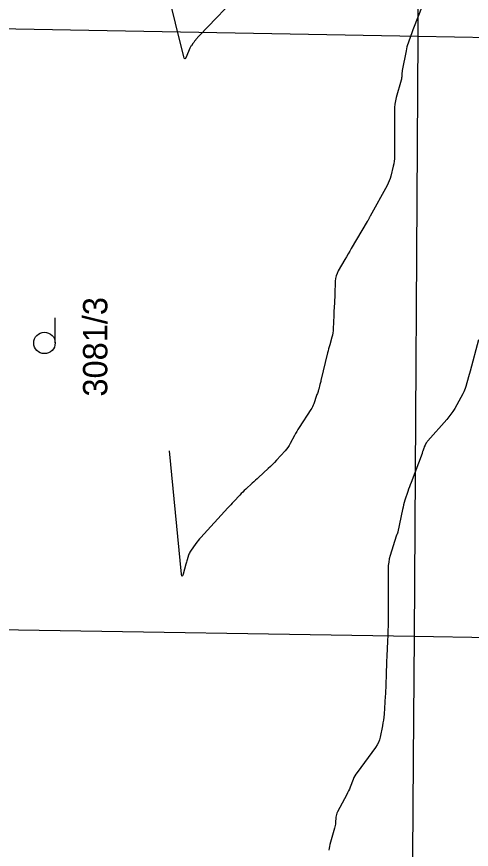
# Model space of a CAD drawing. Extents: x -534410 to -534262, y -1190162 to -1189584.
# Drawn here: x -534356.09 to -534340.2, y -1190052.88 to -1190023.79 of the extents above; entities that cross this region are included whole.
import ezdxf

# ---------------------------------------------------------------- set-up
doc = ezdxf.new("R2010")
doc.units = 0
for name, color, linetype in [('30', 7, 'Continuous'), ('31', 7, 'Continuous'), ('Hranice parcel', 7, 'Continuous'), ('Parcelní čísla', 7, 'Continuous'), ('Značky kultur', 7, 'Continuous')]:
    doc.layers.add(name, color=color, linetype=linetype)

msp = doc.modelspace()

# ---------------------------------------------------------------- linework, layer by layer
at = {"layer": '30'}
msp.add_lwpolyline([(-534341.764, -1190023.028), (-534342.218, -1190024.189), (-534342.243, -1190024.254), (-534342.268, -1190024.319), (-534342.292, -1190024.385), (-534342.315, -1190024.45), (-534342.407, -1190024.713), (-534342.429, -1190024.779), (-534342.448, -1190024.846), (-534342.465, -1190024.913), (-534342.479, -1190024.981), (-534342.613, -1190025.67), (-534342.618, -1190025.698), (-534342.622, -1190025.726), (-534342.625, -1190025.754), (-534342.627, -1190025.782), (-534342.633, -1190025.895), (-534342.635, -1190025.923), (-534342.639, -1190025.951), (-534342.644, -1190025.979), (-534342.651, -1190026.006), (-534342.822, -1190026.621), (-534342.849, -1190026.733), (-534342.868, -1190026.847), (-534342.88, -1190026.961), (-534342.884, -1190027.076), (-534342.884, -1190028.667), (-534342.886, -1190028.756), (-534342.894, -1190028.843), (-534342.908, -1190028.93), (-534342.927, -1190029.017), (-534343.012, -1190029.361), (-534343.036, -1190029.446), (-534343.065, -1190029.529), (-534343.1, -1190029.609), (-534343.141, -1190029.688), (-534343.737, -1190030.764), (-534343.743, -1190030.776), (-534343.749, -1190030.787), (-534343.76, -1190030.81), (-534343.766, -1190030.822), (-534343.772, -1190030.833), (-534343.808, -1190030.898), (-534343.815, -1190030.911), (-534343.822, -1190030.924), (-534343.83, -1190030.936), (-534343.837, -1190030.949), (-534344.393, -1190031.893), (-534344.449, -1190031.988), (-534344.505, -1190032.083), (-534344.56, -1190032.178), (-534344.615, -1190032.273), (-534344.849, -1190032.677), (-534344.891, -1190032.763), (-534344.923, -1190032.851), (-534344.943, -1190032.943), (-534344.952, -1190033.037), (-534344.967, -1190033.493), (-534344.97, -1190033.555), (-534344.972, -1190033.616), (-534344.976, -1190033.678), (-534344.98, -1190033.739), (-534344.997, -1190033.984), (-534345.001, -1190034.045), (-534345.004, -1190034.107), (-534345.007, -1190034.168), (-534345.01, -1190034.23), (-534345.027, -1190034.7), (-534345.031, -1190034.772), (-534345.04, -1190034.843), (-534345.053, -1190034.914), (-534345.071, -1190034.984), (-534345.148, -1190035.262), (-534345.167, -1190035.332), (-534345.185, -1190035.401), (-534345.203, -1190035.471), (-534345.22, -1190035.541), (-534345.453, -1190036.502), (-534345.461, -1190036.537), (-534345.47, -1190036.571), (-534345.479, -1190036.605), (-534345.488, -1190036.639), (-534345.531, -1190036.806), (-534345.537, -1190036.825), (-534345.542, -1190036.844), (-534345.548, -1190036.863), (-534345.555, -1190036.882), (-534345.581, -1190036.956), (-534345.594, -1190036.993), (-534345.607, -1190037.03), (-534345.706, -1190037.315), (-534345.726, -1190037.368), (-534345.749, -1190037.42), (-534345.776, -1190037.47), (-534345.805, -1190037.518), (-534346.218, -1190038.15), (-534346.261, -1190038.217), (-534346.301, -1190038.285), (-534346.341, -1190038.354), (-534346.378, -1190038.423), (-534346.525, -1190038.704), (-534346.564, -1190038.773), (-534346.607, -1190038.839), (-534346.654, -1190038.901), (-534346.706, -1190038.961), (-534347.01, -1190039.292), (-534347.079, -1190039.365), (-534347.15, -1190039.438), (-534347.222, -1190039.508), (-534347.296, -1190039.578), (-534347.632, -1190039.887), (-534347.687, -1190039.938), (-534347.743, -1190039.989), (-534347.799, -1190040.04), (-534347.855, -1190040.091), (-534348.079, -1190040.295), (-534348.134, -1190040.347), (-534348.188, -1190040.399), (-534348.242, -1190040.453), (-534348.294, -1190040.508), (-534348.503, -1190040.733), (-534348.555, -1190040.789), (-534348.606, -1190040.845), (-534348.658, -1190040.901), (-534348.71, -1190040.957), (-534349.651, -1190041.986), (-534349.696, -1190042.036), (-534349.74, -1190042.088), (-534349.782, -1190042.142), (-534349.822, -1190042.196), (-534350.012, -1190042.461), (-534350.034, -1190042.495), (-534350.054, -1190042.531), (-534350.07, -1190042.568), (-534350.083, -1190042.607), (-534350.131, -1190042.765), (-534350.142, -1190042.805), (-534350.154, -1190042.845), (-534350.165, -1190042.884), (-534350.177, -1190042.924), (-534350.274, -1190043.273), (-534350.292, -1190043.326), (-534350.307, -1190043.343), (-534350.319, -1190043.323), (-534350.328, -1190043.268), (-534350.749, -1190038.959)], dxfattribs=at)
at = {"layer": '31'}
for points in [[(-534348.223, -1190022.899), (-534349.701, -1190024.452), (-534349.722, -1190024.474), (-534349.742, -1190024.497), (-534349.763, -1190024.521), (-534349.782, -1190024.544), (-534349.87, -1190024.65), (-534349.885, -1190024.669), (-534349.9, -1190024.688), (-534349.914, -1190024.707), (-534349.928, -1190024.726), (-534349.984, -1190024.805), (-534349.997, -1190024.825), (-534350.009, -1190024.846), (-534350.02, -1190024.867), (-534350.031, -1190024.889), (-534350.169, -1190025.203), (-534350.194, -1190025.247), (-534350.216, -1190025.261), (-534350.235, -1190025.244), (-534350.252, -1190025.196), (-534350.824, -1190022.831)], [(-534339.949, -1190035.085), (-534340.244, -1190036.173), (-534340.299, -1190036.374), (-534340.39, -1190036.71), (-534340.41, -1190036.777), (-534340.434, -1190036.841), (-534340.462, -1190036.904), (-534340.494, -1190036.966), (-534340.781, -1190037.477), (-534340.843, -1190037.581), (-534340.91, -1190037.68), (-534340.982, -1190037.777), (-534341.06, -1190037.869), (-534341.719, -1190038.614), (-534341.731, -1190038.628), (-534341.742, -1190038.643), (-534341.752, -1190038.658), (-534341.762, -1190038.673), (-534341.809, -1190038.75), (-534341.814, -1190038.759), (-534341.819, -1190038.768), (-534341.823, -1190038.777), (-534341.827, -1190038.787), (-534341.842, -1190038.825), (-534341.849, -1190038.845), (-534341.856, -1190038.864), (-534341.893, -1190038.968), (-534341.901, -1190038.989), (-534341.908, -1190039.009), (-534341.916, -1190039.03), (-534341.923, -1190039.05), (-534342.307, -1190040.07), (-534342.335, -1190040.146), (-534342.363, -1190040.223), (-534342.39, -1190040.301), (-534342.416, -1190040.378), (-534342.519, -1190040.689), (-534342.543, -1190040.767), (-534342.566, -1190040.846), (-534342.586, -1190040.925), (-534342.604, -1190041.005), (-534342.766, -1190041.788), (-534342.769, -1190041.802), (-534342.773, -1190041.815), (-534342.778, -1190041.829), (-534342.784, -1190041.842), (-534342.807, -1190041.894), (-534342.812, -1190041.907), (-534342.818, -1190041.92), (-534342.823, -1190041.934), (-534342.827, -1190041.947), (-534343.033, -1190042.613), (-534343.065, -1190042.73), (-534343.087, -1190042.847), (-534343.1, -1190042.966), (-534343.105, -1190043.086), (-534343.105, -1190044.689), (-534343.105, -1190044.767), (-534343.106, -1190044.844), (-534343.107, -1190044.922), (-534343.109, -1190045), (-534343.117, -1190045.311), (-534343.119, -1190045.389), (-534343.122, -1190045.467), (-534343.125, -1190045.544), (-534343.129, -1190045.622), (-534343.155, -1190046.119), (-534343.158, -1190046.191), (-534343.162, -1190046.264), (-534343.164, -1190046.336), (-534343.166, -1190046.409), (-534343.174, -1190046.708), (-534343.176, -1190046.776), (-534343.178, -1190046.844), (-534343.18, -1190046.913), (-534343.183, -1190046.981), (-534343.192, -1190047.255), (-534343.194, -1190047.323), (-534343.198, -1190047.391), (-534343.201, -1190047.459), (-534343.206, -1190047.528), (-534343.25, -1190048.164), (-534343.259, -1190048.265), (-534343.271, -1190048.365), (-534343.287, -1190048.464), (-534343.306, -1190048.564), (-534343.388, -1190048.96), (-534343.414, -1190049.057), (-534343.449, -1190049.149), (-534343.495, -1190049.237), (-534343.55, -1190049.321), (-534344.193, -1190050.193), (-534344.234, -1190050.252), (-534344.27, -1190050.313), (-534344.303, -1190050.377), (-534344.331, -1190050.443), (-534344.434, -1190050.711), (-534344.461, -1190050.777), (-534344.49, -1190050.843), (-534344.521, -1190050.907), (-534344.554, -1190050.971), (-534344.878, -1190051.577), (-534344.899, -1190051.621), (-534344.914, -1190051.666), (-534344.925, -1190051.713), (-534344.931, -1190051.761), (-534344.945, -1190051.956), (-534344.949, -1190052.004), (-534344.957, -1190052.052), (-534344.966, -1190052.1), (-534344.978, -1190052.147), (-534345.141, -1190052.713), (-534345.157, -1190052.779), (-534345.17, -1190052.846), (-534345.178, -1190052.913)]]:
    msp.add_lwpolyline(points, dxfattribs=at)
at = {"layer": 'Hranice parcel'}
for p, q in [((-534366.35, -1190024.04), (-534342.06, -1190024.47)), ((-534342.19, -1190045.44), (-534342.06, -1190024.47)), ((-534342.06, -1190024.47), (-534333.46, -1190024.63)), ((-534366.87, -1190045.04), (-534342.19, -1190045.44)), ((-534342.19, -1190045.44), (-534334.16, -1190045.57))]:
    msp.add_line(p, q, dxfattribs=at)
for points in [[(-534342.06, -1190024.47), (-534342.05, -1190022.37), (-534341.99, -1190003.45)], [(-534342.35, -1190068.22), (-534342.22, -1190049.76), (-534342.19, -1190045.44)]]:
    msp.add_lwpolyline(points, dxfattribs=at)
at = {"layer": 'Značky kultur'}
msp.add_line((-534354.742, -1190035.19), (-534354.742, -1190034.315), dxfattribs=at)
msp.add_circle((-534355.117, -1190035.19), 0.375, dxfattribs=at)

# ---------------------------------------------------------------- texts
at = {"layer": 'Parcelní čísla'}
msp.add_text('3081/3', height=0.85, rotation=90, dxfattribs=at).set_placement((-534352.92, -1190037.064))

doc.saveas('drawing.dxf')
